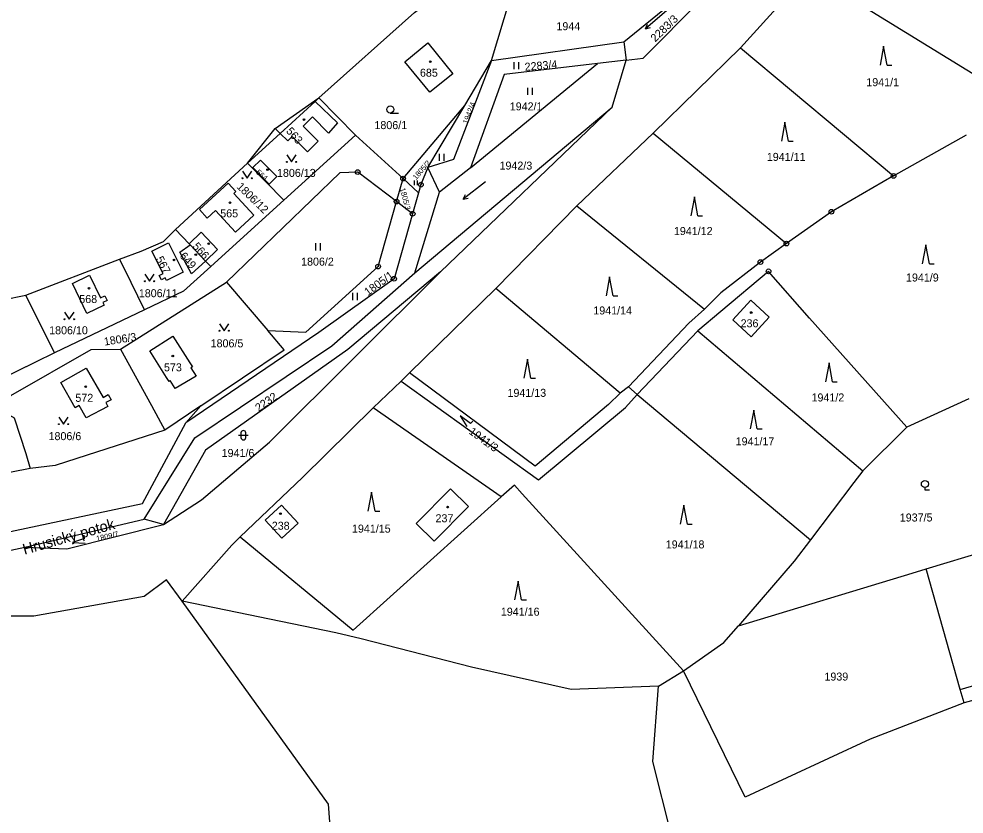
# Model space of a CAD drawing. Extents: x -725728 to -720881, y -1068679 to -1063504.
# Drawn here: x -722836.4 to -722635.6, y -1066784.5 to -1066615.6 of the extents above; entities that cross this region are included whole.
import ezdxf

# ---------------------------------------------------------------- set-up
doc = ezdxf.new("R2010")
doc.units = 0
for name, color, linetype in [('Hranice parcel', 7, 'Continuous'), ('Parcelní čísla', 7, 'Continuous'), ('Pop  PČ popisy', 7, 'Continuous'), ('Vnitřní kresba', 7, 'Continuous'), ('Značky bodu BP', 7, 'Continuous'), ('Značky budov', 7, 'Continuous'), ('Značky kultur', 7, 'Continuous')]:
    doc.layers.add(name, color=color, linetype=linetype)

# ---------------------------------------------------------------- blocks, each defined once
blk = doc.blocks.new('4.02_3')
at = {"layer": 'Značky budov'}
blk.add_circle((-0.001, 0), 0.0175, dxfattribs=at)
blk = doc.blocks.new('4.02_4')
at = {"layer": 'Značky budov'}
blk.add_circle((-0.001, 0), 0.0175, dxfattribs=at)
blk = doc.blocks.new('3.06_1')
at = {"layer": 'Značky kultur'}
for p, q in [((-0.051, 0), (-0.051, 0.15)), ((0.049, 0), (0.049, 0.15))]:
    blk.add_line(p, q, dxfattribs=at)
blk = doc.blocks.new('3.06_3')
at = {"layer": 'Značky kultur'}
for p, q in [((-0.034, 0), (-0.034, 0.1)), ((0.033, 0), (0.033, 0.1))]:
    blk.add_line(p, q, dxfattribs=at)
blk = doc.blocks.new('3.14_1')
at = {"layer": 'Značky kultur'}
blk.add_lwpolyline([(-0.1, 0.15), (0, 0), (0.1, 0.15)], dxfattribs=at)
for centre in [(-0.1, 0), (0.1, 0)]:
    blk.add_circle(centre, 0.01, dxfattribs=at)
blk = doc.blocks.new('3.14_2')
at = {"layer": 'Značky kultur'}
blk.add_lwpolyline([(-0.1, 0.15), (0, 0), (0.1, 0.15)], dxfattribs=at)
for centre in [(-0.1, 0), (0.1, 0)]:
    blk.add_circle(centre, 0.01, dxfattribs=at)
blk = doc.blocks.new('3.04_2')
at = {"layer": 'Značky kultur'}
blk.add_line((0.001, 0), (0.176, 0), dxfattribs=at)
blk.add_circle((0.001, 0.075), 0.075, dxfattribs=at)
blk = doc.blocks.new('1.05_2')
at = {"layer": 'Značky bodu BP'}
for radius in [0.05, 0.00303]:
    blk.add_circle((0, 0), radius, dxfattribs=at)
blk = doc.blocks.new('1.05_1')
at = {"layer": 'Značky bodu BP'}
for radius in [0.05, 0.00303]:
    blk.add_circle((0, 0), radius, dxfattribs=at)

msp = doc.modelspace()

# ---------------------------------------------------------------- linework, layer by layer
at = {"layer": 'Hranice parcel'}
for p, q in [((-722668.68, -1066605.74), (-722683.05, -1066621.74)), ((-722629.8, -1066629.67), (-722668.68, -1066605.74)), ((-722735.96, -1066624.41), (-722731.13, -1066608.27)), ((-722735.96, -1066624.41), (-722731.13, -1066608.27)), ((-722707.84, -1066620.47), (-722697.34, -1066611.86)), ((-722735.96, -1066624.41), (-722707.84, -1066620.47)), ((-722707.84, -1066620.47), (-722707.36, -1066624.35)), ((-722683.05, -1066621.74), (-722701.6, -1066639.88)), ((-722683.05, -1066621.74), (-722650.55, -1066648.94)), ((-722741.62, -1066633.95), (-722735.96, -1066624.41)), ((-722741.62, -1066633.95), (-722735.96, -1066624.41)), ((-722707.36, -1066624.35), (-722713.46, -1066625.08)), ((-722710.35, -1066634.32), (-722707.36, -1066624.35)), ((-722740.42, -1066647.19), (-722713.46, -1066625.08)), ((-722773.46, -1066633.11), (-722772.64, -1066632.36)), ((-722772.64, -1066632.36), (-722764.89, -1066640.27)), ((-722780.86, -1066639.89), (-722773.46, -1066633.11)), ((-722754.76, -1066649.51), (-722741.62, -1066633.95)), ((-722752.24, -1066669.52), (-722710.35, -1066634.32)), ((-722749.48, -1066647.17), (-722741.62, -1066633.95)), ((-722749.48, -1066647.17), (-722741.62, -1066633.95)), ((-722746.83, -1066669.34), (-722710.35, -1066634.32)), ((-722787.81, -1066646.24), (-722780.86, -1066639.89)), ((-722764.89, -1066640.27), (-722780.11, -1066654.07)), ((-722764.89, -1066640.27), (-722754.76, -1066649.51)), ((-722701.6, -1066639.88), (-722717.83, -1066655.31)), ((-722701.6, -1066639.88), (-722673.3, -1066663.31)), ((-722650.55, -1066648.94), (-722635.06, -1066640.22)), ((-722803.1, -1066660.33), (-722787.81, -1066646.24)), ((-722780.11, -1066654.07), (-722787.81, -1066646.24)), ((-722756.15, -1066654.38), (-722764.4, -1066648.11)), ((-722749.48, -1066647.17), (-722750.97, -1066650.79)), ((-722747, -1066652.41), (-722749.48, -1066647.17)), ((-722747, -1066652.41), (-722749.48, -1066647.17)), ((-722740.42, -1066647.19), (-722747, -1066652.41)), ((-722756.15, -1066654.38), (-722754.76, -1066649.51)), ((-722754.76, -1066649.51), (-722751.46, -1066652.52)), ((-722750.97, -1066650.79), (-722751.46, -1066652.52)), ((-722751.46, -1066652.52), (-722752.73, -1066656.98)), ((-722752.24, -1066669.52), (-722747, -1066652.41)), ((-722752.24, -1066669.52), (-722747, -1066652.41)), ((-722780.11, -1066654.07), (-722795.64, -1066668.18)), ((-722760.08, -1066668.18), (-722756.15, -1066654.38)), ((-722752.73, -1066656.98), (-722756.15, -1066654.38)), ((-722752.73, -1066656.98), (-722756.67, -1066670.78)), ((-722717.83, -1066655.31), (-722735.04, -1066672.82)), ((-722717.83, -1066655.31), (-722690.74, -1066677.22)), ((-722800.22, -1066663.36), (-722803.1, -1066660.33)), ((-722800, -1066663.59), (-722800.22, -1066663.36)), ((-722800, -1066663.59), (-722796.75, -1066667.01)), ((-722834.89, -1066674.24), (-722815, -1066666.58)), ((-722795.64, -1066668.18), (-722796.75, -1066667.01)), ((-722769.92, -1066685.03), (-722752.24, -1066669.52)), ((-722769.92, -1066685.03), (-722752.24, -1066669.52)), ((-722814.82, -1066685.75), (-722792.29, -1066671.51)), ((-722792.29, -1066671.51), (-722783.47, -1066681.8)), ((-722735.04, -1066672.82), (-722753.38, -1066690.75)), ((-722708.67, -1066695.05), (-722735.04, -1066672.82)), ((-722828.81, -1066686.53), (-722834.89, -1066674.24)), ((-722705, -1066695.37), (-722692.13, -1066681.81)), ((-722692.13, -1066681.81), (-722657.1, -1066711.58)), ((-722798.98, -1066704.54), (-722769.92, -1066685.03)), ((-722798.98, -1066704.54), (-722769.92, -1066685.03)), ((-722828.81, -1066686.53), (-722848.57, -1066696.11)), ((-722753.38, -1066690.75), (-722755.2, -1066692.5)), ((-722755.2, -1066692.5), (-722761.11, -1066698.16)), ((-722706.88, -1066693.73), (-722708.67, -1066695.05)), ((-722705, -1066695.37), (-722706.88, -1066693.73)), ((-722705, -1066695.37), (-722668.22, -1066726.23)), ((-722634.59, -1066696.27), (-722647.75, -1066702.28)), ((-722797.75, -1066697.8), (-722805.36, -1066702.93)), ((-722800.94, -1066701.38), (-722797.75, -1066697.8)), ((-722733.91, -1066717.09), (-722761.11, -1066698.16)), ((-722647.75, -1066702.28), (-722657.1, -1066711.58)), ((-722809.75, -1066721.84), (-722798.98, -1066704.54)), ((-722809.75, -1066721.84), (-722798.98, -1066704.54)), ((-722835.11, -1066727.8), (-722809.75, -1066721.84)), ((-722835.11, -1066727.8), (-722809.75, -1066721.84)), ((-722805.67, -1066722.95), (-722809.75, -1066721.84)), ((-722840.77, -1066728.98), (-722835.11, -1066727.8)), ((-722840.77, -1066728.98), (-722835.11, -1066727.8)), ((-722643.65, -1066732.41), (-722630.39, -1066728.39)), ((-722636.39, -1066758.01), (-722643.65, -1066732.41)), ((-722700.51, -1066757.29), (-722695.18, -1066754.09)), ((-722635.57, -1066760.89), (-722636.39, -1066758.01))]:
    msp.add_line(p, q, dxfattribs=at)
for points in [[(-722772.64, -1066632.36), (-722752.34, -1066614.22), (-722735.78, -1066601.73)], [(-722707.36, -1066624.35), (-722703.77, -1066623.92), (-722691.41, -1066611.44)], [(-722749.06, -1066631.11), (-722754.37, -1066624.69), (-722749.49, -1066620.64), (-722744.22, -1066627.26), (-722749.06, -1066631.11)], [(-722735.96, -1066624.41), (-722744.05, -1066645.42), (-722749.48, -1066647.17)], [(-722713.46, -1066625.08), (-722733.25, -1066627.39), (-722740.42, -1066647.19)], [(-722773.46, -1066633.11), (-722768.69, -1066637.65), (-722770.6, -1066639.83), (-722774.03, -1066636.37), (-722776.01, -1066638.35), (-722772.79, -1066641.57), (-722775.05, -1066643.83), (-722778.31, -1066640.58), (-722779.24, -1066641.51), (-722780.86, -1066639.89)], [(-722781.57, -1066649.09), (-722783.21, -1066650.7), (-722786.69, -1066647.17), (-722785.05, -1066645.56), (-722781.57, -1066649.09)], [(-722764.4, -1066648.11), (-722768.19, -1066648.3), (-722792.29, -1066671.51)], [(-722650.55, -1066648.94), (-722663.76, -1066656.53), (-722673.3, -1066663.31)], [(-722790.72, -1066652.66), (-722786.45, -1066657.29), (-722790.35, -1066660.89), (-722794.62, -1066656.25), (-722796.38, -1066657.88), (-722798.04, -1066656.08), (-722791.96, -1066650.47), (-722790.3, -1066652.27), (-722790.72, -1066652.66)], [(-722815, -1066666.58), (-722810.41, -1066664.89), (-722805.68, -1066662.87), (-722804.96, -1066662.16), (-722803.1, -1066660.33)], [(-722800.22, -1066663.36), (-722797.63, -1066660.9), (-722794.2, -1066664.59), (-722796.75, -1066667.01)], [(-722805.3, -1066670.61), (-722806.09, -1066671), (-722806.56, -1066670.08), (-722805.77, -1066669.68), (-722808.14, -1066664.95), (-722804.59, -1066663.17), (-722801.46, -1066669.39), (-722805.02, -1066671.18), (-722805.3, -1066670.61)], [(-722796.75, -1066667.01), (-722799.72, -1066669.7), (-722802.19, -1066665.11), (-722800, -1066663.59)], [(-722673.3, -1066663.31), (-722678.84, -1066667.25), (-722687.27, -1066673.77), (-722690.74, -1066677.22)], [(-722809.67, -1066677.39), (-722813.97, -1066668.68), (-722815, -1066666.58)], [(-722795.64, -1066668.18), (-722801.44, -1066673.43), (-722809.67, -1066677.39)], [(-722783.47, -1066681.8), (-722775.46, -1066682.14), (-722760.08, -1066668.18)], [(-722819.02, -1066674.86), (-722818.11, -1066674.43), (-722817.64, -1066675.42), (-722818.54, -1066675.85), (-722818.28, -1066676.39), (-722821.95, -1066678.16), (-722825.03, -1066671.76), (-722821.36, -1066669.99), (-722819.02, -1066674.86)], [(-722746.83, -1066669.34), (-722766.49, -1066685.82), (-722796.77, -1066707.19), (-722805.67, -1066722.95)], [(-722805.67, -1066722.95), (-722797.59, -1066717.75), (-722783.15, -1066705.5), (-722746.83, -1066669.34)], [(-722756.67, -1066670.78), (-722772.68, -1066682.2), (-722800.94, -1066701.38)], [(-722647.75, -1066702.28), (-722668.38, -1066679.15), (-722677.12, -1066669.2), (-722687.27, -1066677.72), (-722692.13, -1066681.81)], [(-722853.99, -1066683.41), (-722852.06, -1066680.95), (-722846.94, -1066678.73), (-722845.81, -1066678.15), (-722839.82, -1066675.28), (-722834.89, -1066674.24)], [(-722680.82, -1066683.11), (-722684.73, -1066679.48), (-722680.87, -1066675.32), (-722676.96, -1066678.95), (-722680.82, -1066683.11)], [(-722809.67, -1066677.39), (-722822.43, -1066683.46), (-722828.81, -1066686.53)], [(-722690.74, -1066677.22), (-722694.03, -1066680.2), (-722706.88, -1066693.73)], [(-722799.86, -1066689.7), (-722798.74, -1066691.47), (-722803.17, -1066694.09), (-722804.24, -1066692.41), (-722804.49, -1066692.57), (-722805.02, -1066691.72), (-722808.6, -1066686.07), (-722803.66, -1066682.95), (-722800.08, -1066688.62), (-722799.53, -1066689.49), (-722799.86, -1066689.7)], [(-722797.75, -1066697.8), (-722780, -1066685.85), (-722783.47, -1066681.8)], [(-722841.27, -1066698.12), (-722838.11, -1066695.56), (-722821.01, -1066685.8), (-722814.82, -1066685.75)], [(-722814.82, -1066685.75), (-722808.25, -1066697.68), (-722805.36, -1066702.93)], [(-722827.48, -1066692.83), (-722822.07, -1066689.8), (-722818.52, -1066696.01), (-722817.44, -1066695.39), (-722816.82, -1066696.47), (-722817.9, -1066697.09), (-722817.46, -1066697.88), (-722822.09, -1066700.35), (-722823.6, -1066697.7), (-722824.43, -1066698.17), (-722827.48, -1066692.83)], [(-722708.67, -1066695.05), (-722711.13, -1066697.49), (-722726.7, -1066710.56), (-722753.38, -1066690.75)], [(-722755.2, -1066692.5), (-722726.02, -1066713.5), (-722707.48, -1066698.1), (-722705, -1066695.37)], [(-722841.27, -1066698.12), (-722837.36, -1066700.35), (-722834.89, -1066707.91), (-722834.01, -1066711.05)], [(-722761.11, -1066698.16), (-722776.15, -1066713.02), (-722789.38, -1066725.61)], [(-722991.14, -1066761.64), (-722981.78, -1066735.19), (-722964.23, -1066729.87), (-722951.74, -1066726.08), (-722943.35, -1066719.22), (-722934.73, -1066712.18), (-722898.44, -1066706.54), (-722860.47, -1066714.93), (-722839.51, -1066724.75), (-722810.16, -1066718.52), (-722800.94, -1066701.38)], [(-722805.36, -1066702.93), (-722824.06, -1066708.99), (-722828.67, -1066710.44), (-722834.01, -1066711.05)], [(-722834.01, -1066711.05), (-722842.02, -1066712.66), (-722854.9, -1066713.62), (-722863.23, -1066713.8), (-722870.42, -1066711.78), (-722873.84, -1066710.47), (-722877.16, -1066707.27)], [(-722657.1, -1066711.58), (-722658.98, -1066714.06), (-722668.22, -1066726.23)], [(-722695.18, -1066754.09), (-722729.43, -1066716.44), (-722731.11, -1066714.59), (-722733.91, -1066717.09)], [(-722789.38, -1066725.61), (-722765.34, -1066745.39), (-722733.91, -1066717.09)], [(-722740.88, -1066719.13), (-722748.19, -1066726.55), (-722752, -1066722.8), (-722744.69, -1066715.38), (-722740.88, -1066719.13)], [(-722780.58, -1066718.85), (-722777.04, -1066722.7), (-722780.5, -1066725.88), (-722784.04, -1066722.03), (-722780.58, -1066718.85)], [(-722835.11, -1066727.8), (-722826.17, -1066728.16), (-722805.67, -1066722.95)], [(-722789.38, -1066725.61), (-722791.14, -1066727.39), (-722801.67, -1066739.27)], [(-722668.22, -1066726.23), (-722671.7, -1066730.74), (-722683.49, -1066744.5)], [(-722683.49, -1066744.5), (-722646.59, -1066733.3), (-722643.65, -1066732.41)], [(-722801.67, -1066739.27), (-722805.03, -1066734.72), (-722809.75, -1066738.3), (-722833.19, -1066742.45), (-722861.5, -1066742.45), (-722873.51, -1066740.45), (-722882.23, -1066736.73), (-722898.38, -1066734.58), (-722910.82, -1066735.87), (-722918.54, -1066739.73), (-722929.09, -1066747.52), (-722936.53, -1066753.01), (-722940.11, -1066755.66), (-722945.85, -1066759.89), (-722947.79, -1066761.91), (-722953.57, -1066767.9), (-722968, -1066791.78)], [(-722720.59, -1066888.57), (-722751.29, -1066847.05), (-722769.02, -1066803.11), (-722770.64, -1066782.4), (-722801.67, -1066739.27)], [(-722700.51, -1066757.29), (-722719.02, -1066758.02), (-722740.21, -1066753.31), (-722763.65, -1066747.25), (-722769.04, -1066745.97), (-722801.67, -1066739.27)], [(-722695.18, -1066754.09), (-722686.59, -1066748.07), (-722683.49, -1066744.5)], [(-722636.39, -1066758.01), (-722615.93, -1066752.03), (-722580.2, -1066744.25), (-722564.85, -1066743.47)], [(-722575.1, -1066746), (-722613.86, -1066754.97), (-722635.57, -1066760.89)], [(-722635.57, -1066760.89), (-722655.52, -1066768.6), (-722682.09, -1066780.88), (-722695.18, -1066754.09)], [(-722671.59, -1066850.57), (-722697.82, -1066788.78), (-722701.69, -1066773.29), (-722700.51, -1066757.29)]]:
    msp.add_lwpolyline(points, dxfattribs=at)
at = {"layer": 'Vnitřní kresba'}
for p, q in [((-722773.6, -1066632.97), (-722772.64, -1066632.36)), ((-722781.92, -1066638.83), (-722773.6, -1066632.97)), ((-722773.6, -1066632.97), (-722773.46, -1066633.11)), ((-722787.81, -1066646.24), (-722781.92, -1066638.83)), ((-722781.92, -1066638.83), (-722780.86, -1066639.89))]:
    msp.add_line(p, q, dxfattribs=at)
at = {"layer": 'Značky bodu BP'}
for centre, radius in [((-722650.55, -1066648.94), 0.5), ((-722650.55, -1066648.94), 0.0303), ((-722663.76, -1066656.53), 0.5), ((-722663.76, -1066656.53), 0.0303), ((-722673.3, -1066663.31), 0.5), ((-722673.3, -1066663.31), 0.0303), ((-722678.84, -1066667.25), 0.5), ((-722678.84, -1066667.25), 0.0303), ((-722677.12, -1066669.2), 0.5), ((-722677.12, -1066669.2), 0.0303)]:
    msp.add_circle(centre, radius, dxfattribs=at)
at = {"layer": 'Značky budov'}
for centre in [(-722680.8, -1066677.96), (-722745.3, -1066719.28), (-722780.81, -1066720.66)]:
    msp.add_circle(centre, 0.175, dxfattribs=at)
at = {"layer": 'Značky kultur'}
for p, q in [((-722698.72, -1066613.77), (-722703.25, -1066617.7)), ((-722703.25, -1066617.7), (-722702.84, -1066616.68)), ((-722703.25, -1066617.7), (-722702.19, -1066617.44)), ((-722652.66, -1066621.4), (-722653.41, -1066625.4)), ((-722651.91, -1066625.4), (-722652.66, -1066621.4)), ((-722731.16, -1066626.25), (-722731.16, -1066624.75)), ((-722730.16, -1066626.25), (-722730.16, -1066624.75)), ((-722651.91, -1066625.4), (-722650.91, -1066625.4)), ((-722728.28, -1066631.74), (-722728.28, -1066630.24)), ((-722727.28, -1066631.74), (-722727.28, -1066630.24)), ((-722673.64, -1066637.52), (-722674.39, -1066641.52)), ((-722672.89, -1066641.52), (-722673.64, -1066637.52)), ((-722672.89, -1066641.52), (-722671.89, -1066641.52)), ((-722747.06, -1066645.73), (-722747.06, -1066644.23)), ((-722746.06, -1066645.73), (-722746.06, -1066644.23)), ((-722737.26, -1066650.19), (-722741.98, -1066653.88)), ((-722741.98, -1066653.88), (-722741.52, -1066652.88)), ((-722741.98, -1066653.88), (-722740.9, -1066653.67)), ((-722692.88, -1066653.39), (-722693.63, -1066657.39)), ((-722692.13, -1066657.39), (-722692.88, -1066653.39)), ((-722692.13, -1066657.39), (-722691.13, -1066657.39)), ((-722643.69, -1066663.58), (-722644.44, -1066667.58)), ((-722642.94, -1066667.58), (-722643.69, -1066663.58)), ((-722642.94, -1066667.58), (-722641.94, -1066667.58)), ((-722710.87, -1066670.39), (-722711.62, -1066674.39)), ((-722710.12, -1066674.39), (-722710.87, -1066670.39)), ((-722710.12, -1066674.39), (-722709.12, -1066674.39)), ((-722728.36, -1066687.88), (-722729.11, -1066691.88)), ((-722727.61, -1066691.88), (-722728.36, -1066687.88)), ((-722664.26, -1066688.64), (-722665.01, -1066692.64)), ((-722663.51, -1066692.64), (-722664.26, -1066688.64)), ((-722727.61, -1066691.88), (-722726.61, -1066691.88)), ((-722663.51, -1066692.64), (-722662.51, -1066692.64)), ((-722680.25, -1066698.67), (-722681, -1066702.67)), ((-722679.5, -1066702.67), (-722680.25, -1066698.67)), ((-722740.46, -1066701.51), (-722742.66, -1066699.89)), ((-722742.66, -1066699.89), (-722741.2, -1066702.19)), ((-722740.46, -1066701.51), (-722739.97, -1066701.05)), ((-722679.5, -1066702.67), (-722678.5, -1066702.67)), ((-722789.7, -1066704.02), (-722787.7, -1066704.02)), ((-722789.2, -1066703.52), (-722789.2, -1066704.52)), ((-722788.2, -1066704.52), (-722788.2, -1066703.52)), ((-722643.89, -1066715.12), (-722643.89, -1066715.62)), ((-722761.47, -1066716.13), (-722762.22, -1066720.13)), ((-722760.72, -1066720.13), (-722761.47, -1066716.13)), ((-722643.89, -1066715.62), (-722642.89, -1066715.62)), ((-722695.11, -1066718.89), (-722695.86, -1066722.89)), ((-722694.36, -1066722.89), (-722695.11, -1066718.89)), ((-722760.72, -1066720.13), (-722759.72, -1066720.13)), ((-722694.36, -1066722.89), (-722693.36, -1066722.89)), ((-722822.42, -1066725.92), (-722822.51, -1066725.26)), ((-722822.42, -1066725.92), (-722825, -1066726.79)), ((-722825, -1066726.79), (-722822.28, -1066726.92)), ((-722730.32, -1066735), (-722731.07, -1066739)), ((-722729.57, -1066739), (-722730.32, -1066735)), ((-722729.57, -1066739), (-722728.57, -1066739))]:
    msp.add_line(p, q, dxfattribs=at)
msp.add_circle((-722643.89, -1066714.37), 0.75, dxfattribs=at)
for centre, start, end in [((-722788.7, -1066703.52), 0, 180), ((-722788.7, -1066704.52), 180, 359.9879)]:
    msp.add_arc(centre, 0.5, start, end, dxfattribs=at)

# ---------------------------------------------------------------- block references
at = {"layer": 'Značky bodu BP', "xscale": 10, "yscale": 10}
for name, p in [('1.05_1', (-722764.4, -1066648.11)), ('1.05_1', (-722754.76, -1066649.51)), ('1.05_1', (-722750.97, -1066650.79)), ('1.05_2', (-722756.15, -1066654.38)), ('1.05_1', (-722752.73, -1066656.98)), ('1.05_2', (-722760.08, -1066668.18)), ('1.05_1', (-722756.67, -1066670.78))]:
    msp.add_blockref(name, p, dxfattribs=at)
at = {"layer": 'Značky budov', "xscale": 10, "yscale": 10}
for name, p in [('4.02_4', (-722748.97, -1066624.67)), ('4.02_3', (-722775.8, -1066636.96)), ('4.02_3', (-722783.55, -1066647.61)), ('4.02_3', (-722791.54, -1066654.62)), ('4.02_3', (-722796.05, -1066663.33)), ('4.02_3', (-722803.41, -1066666.78)), ('4.02_4', (-722798.79, -1066665.65)), ('4.02_3', (-722821.47, -1066672.79)), ('4.02_3', (-722803.68, -1066687.19)), ('4.02_3', (-722822.19, -1066693.71))]:
    msp.add_blockref(name, p, dxfattribs=at)
at = {"layer": 'Značky kultur', "xscale": 10, "yscale": 10}
for name, p in [('3.04_2', (-722757.49, -1066635.57)), ('3.14_1', (-722778.46, -1066645.97)), ('3.14_1', (-722787.91, -1066649.44)), ('3.06_3', (-722752.02, -1066650.88)), ('3.06_1', (-722772.8, -1066664.75)), ('3.14_1', (-722808.62, -1066671.3)), ('3.06_1', (-722764.91, -1066675.29)), ('3.14_2', (-722825.68, -1066679.39)), ('3.14_1', (-722792.79, -1066681.83)), ('3.14_2', (-722826.9, -1066701.66))]:
    msp.add_blockref(name, p, dxfattribs=at)

# ---------------------------------------------------------------- texts
at = {"layer": 'Parcelní čísla'}
for s, height, rotation, p in [('2283/3', 1.7, 44, (-722701.19, -1066620.6)), ('2283/4', 1.7, 5, (-722728.85, -1066626.63)), ('1942/4', 1.14, 69, (-722741.07, -1066638.02)), ('563', 1.7, 312, (-722779.73, -1066639.51)), ('1805/2', 1.14, 49, (-722751.99, -1066649.86)), ('564', 1.14, 319, (-722786.11, -1066648.32)), ('1806/12', 1.7, 316, (-722790.26, -1066651.36)), ('1805/3', 1.14, 285, (-722755.46, -1066651.63)), ('566', 1.7, 312, (-722799.61, -1066663.99)), ('567', 1.7, 298, (-722807.36, -1066666.54)), ('649', 1.7, 312, (-722802.35, -1066666.04)), ('1805/1', 1.7, 36, (-722762.24, -1066674.48)), ('1806/3', 1.7, 9, (-722818.19, -1066684.99)), ('2232', 1.7, 35, (-722785.45, -1066699.08)), ('1941/3', 1.7, 324, (-722740.93, -1066703.57)), ('1809/7', 1.14, 13, (-722819.82, -1066726.57))]:
    msp.add_text(s, height=height, rotation=rotation, dxfattribs=at).set_placement(p)
for s, p in [('1944', (-722722.18, -1066617.98)), ('685', (-722751.18, -1066627.86)), ('1941/1', (-722656.34, -1066629.87)), ('1942/1', (-722732.1, -1066635.01)), ('1806/1', (-722760.85, -1066638.99)), ('1941/11', (-722677.48, -1066645.74)), ('1942/3', (-722734.27, -1066647.59)), ('1806/13', (-722781.55, -1066649.14)), ('565', (-722793.61, -1066657.73)), ('1941/12', (-722697.22, -1066661.49)), ('1806/2', (-722776.43, -1066667.99)), ('1941/9', (-722647.91, -1066671.36)), ('1806/11', (-722810.91, -1066674.7)), ('568', (-722823.56, -1066675.93)), ('1941/14', (-722714.34, -1066678.36)), ('1806/10', (-722829.96, -1066682.57)), ('236', (-722683.05, -1066681.09)), ('1806/5', (-722795.65, -1066685.34)), ('573', (-722805.56, -1066690.44)), ('1941/13', (-722732.58, -1066695.86)), ('1941/2', (-722667.98, -1066696.84)), ('572', (-722824.39, -1066696.92)), ('1806/6', (-722830.09, -1066705.06)), ('1941/17', (-722684.1, -1066706.16)), ('1941/6', (-722793.31, -1066708.64)), ('237', (-722747.87, -1066722.5)), ('1937/5', (-722649.23, -1066722.34)), ('238', (-722782.66, -1066724.09)), ('1941/15', (-722765.62, -1066724.7)), ('1941/18', (-722698.95, -1066728.06)), ('1941/16', (-722733.99, -1066742.35)), ('1939', (-722665.24, -1066756.13))]:
    msp.add_text(s, height=1.7, dxfattribs=at).set_placement(p)
at = {"layer": 'Pop  PČ popisy'}
msp.add_text('Hrusický potok', height=2.3, rotation=16, dxfattribs=at).set_placement((-722835.2, -1066729.42))

doc.saveas('drawing.dxf')
